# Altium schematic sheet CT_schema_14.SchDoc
size 390 x 385 mm
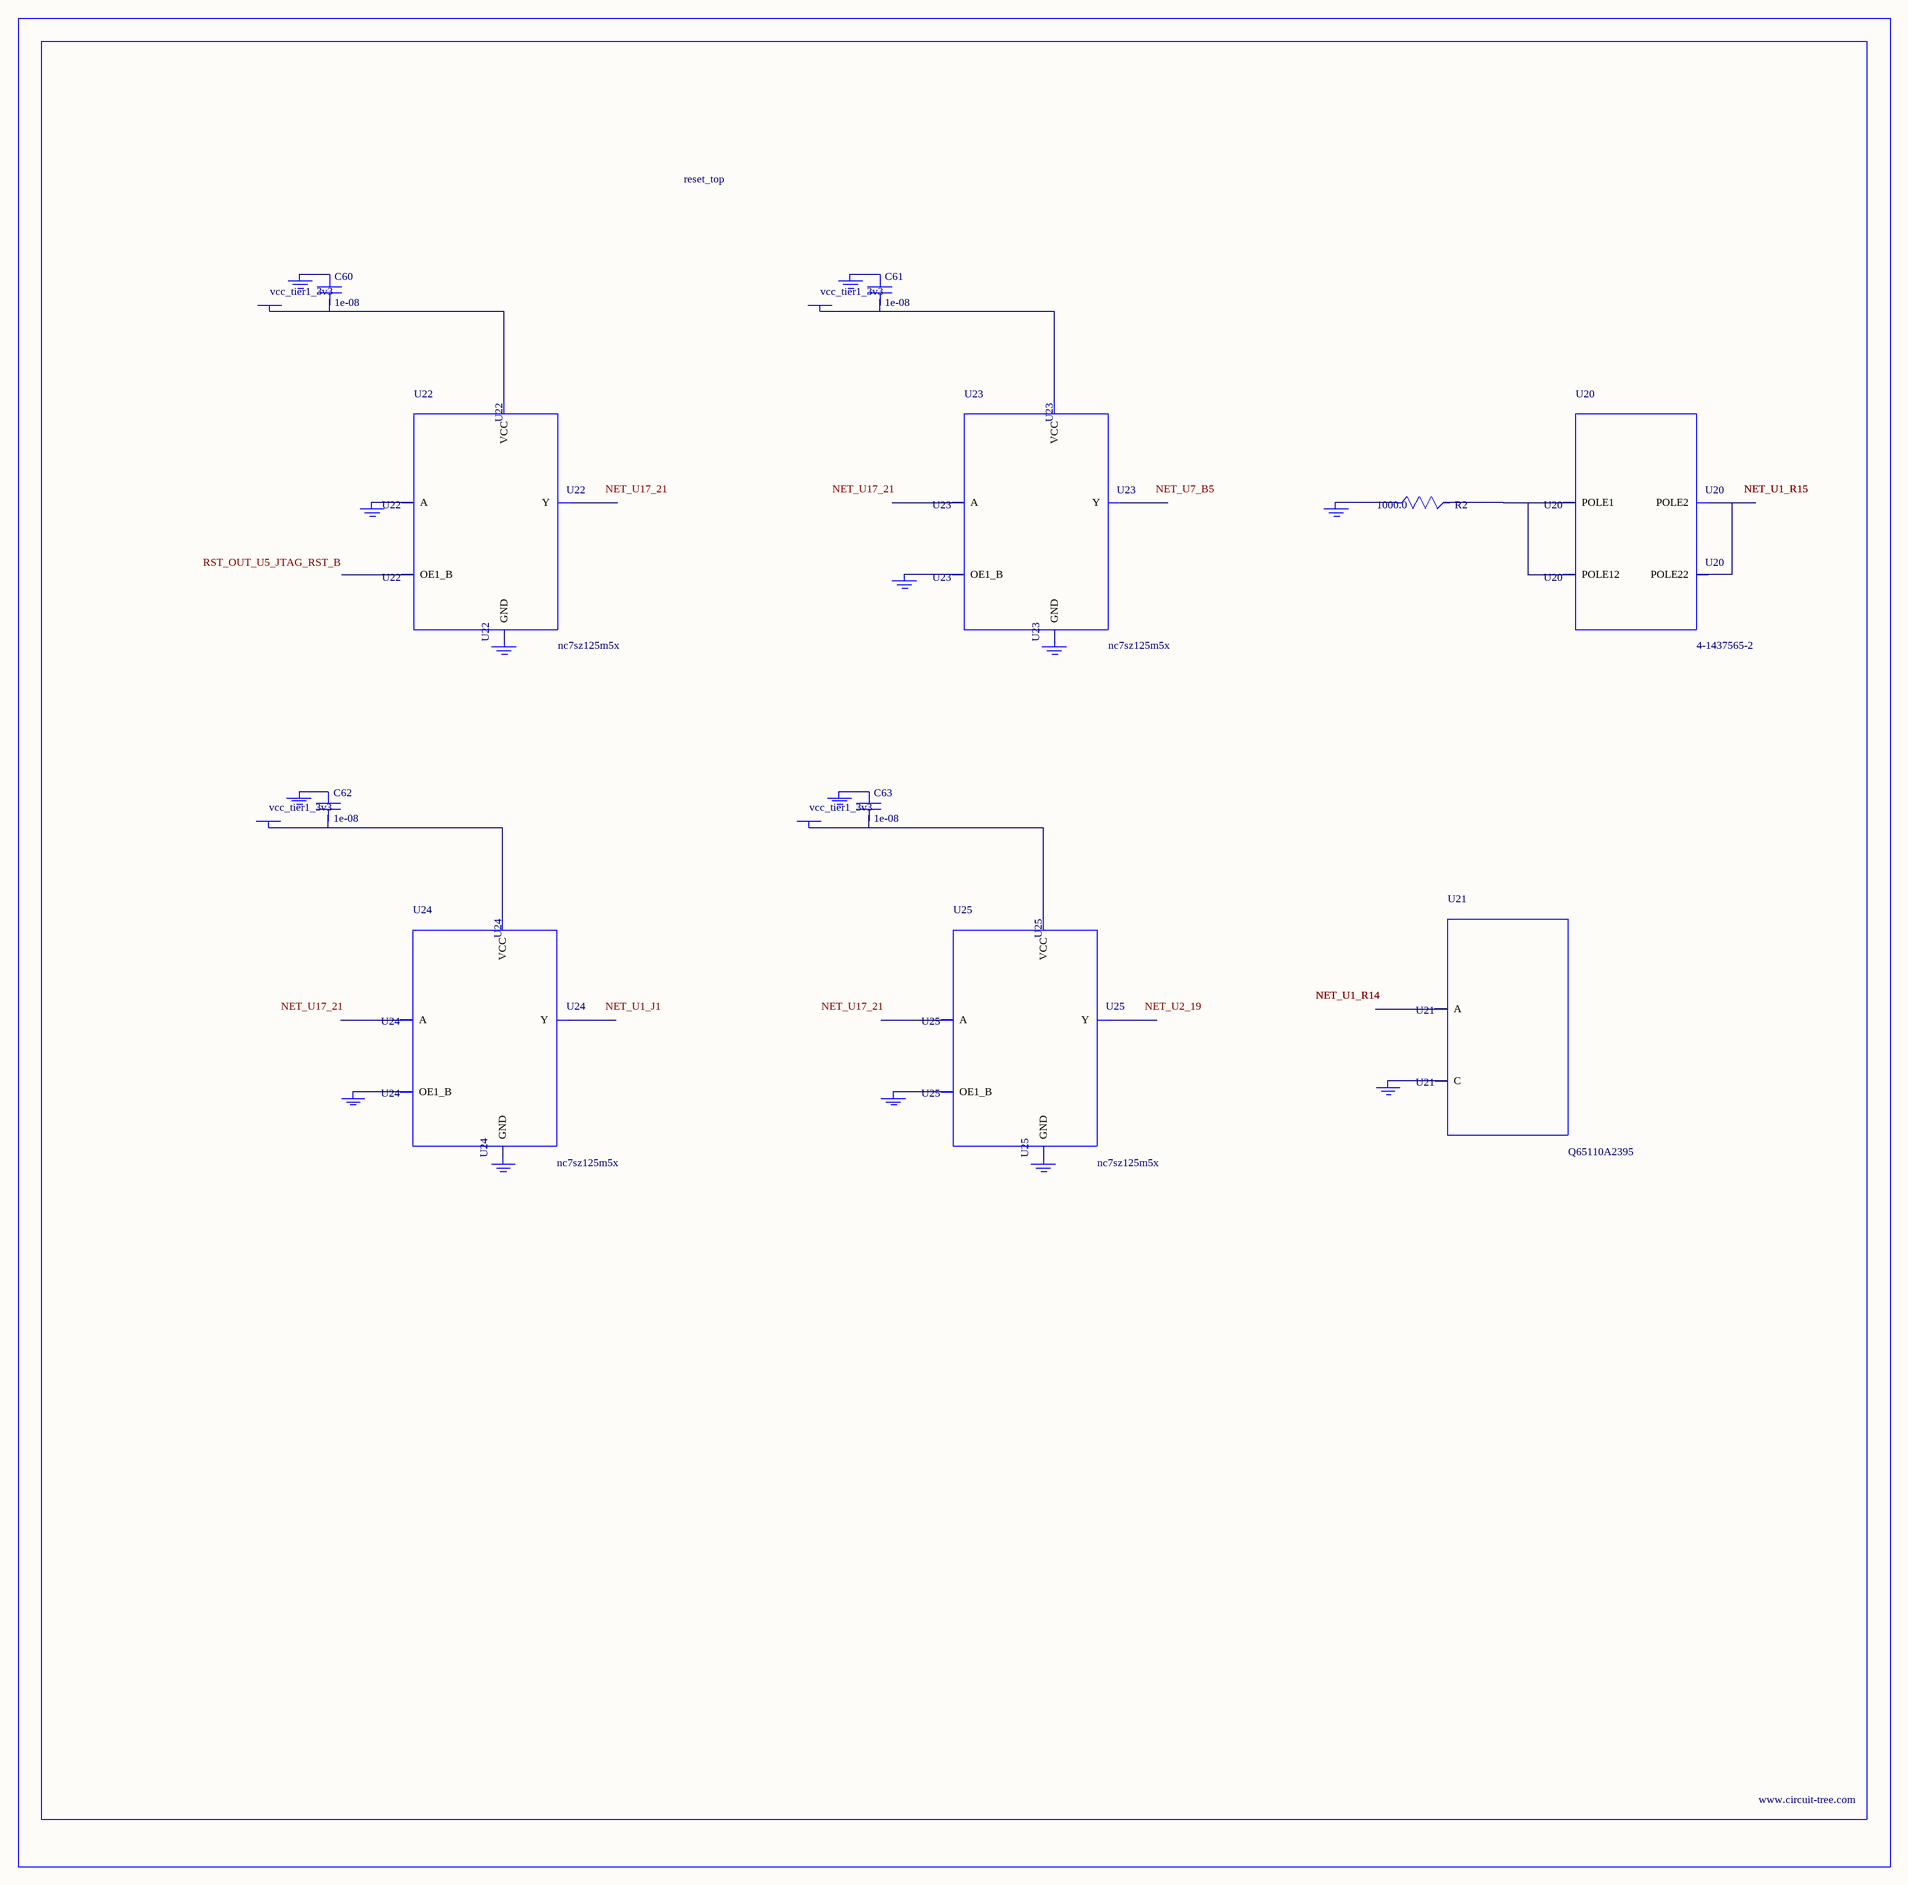
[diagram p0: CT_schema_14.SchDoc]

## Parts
BORDER13  (no value)
C60  1e-08  [C0402]
C61  1e-08  [C0402]
C62  1e-08  [C0402]
C63  1e-08  [C0402]
GND_INSTANCE_13_0  (no value)
GND_INSTANCE_13_1  (no value)
GND_INSTANCE_13_2  (no value)
GND_INSTANCE_13_3  (no value)
GND_INSTANCE_13_4  (no value)
GND_INSTANCE_13_5  (no value)
GND_INSTANCE_13_6  (no value)
GND_INSTANCE_13_7  (no value)
GND_INSTANCE_13_8  (no value)
GND_INSTANCE_13_9  (no value)
GND_INSTANCE_13_10  (no value)
GND_INSTANCE_13_11  (no value)
GND_INSTANCE_13_12  (no value)
GND_INSTANCE_13_13  (no value)
POWER_INSTANCE_13_0  vcc_tier1_3v3
POWER_INSTANCE_13_1  vcc_tier1_3v3
POWER_INSTANCE_13_2  vcc_tier1_3v3
POWER_INSTANCE_13_3  vcc_tier1_3v3
R2  1000.0  [R0603]
U20  4-1437565-2  [SW_4-1437565-2]
U21  Q65110A2395  [LGM67K-G1J2-24-Z]
U22  nc7sz125m5x  [NC7SZ125M5X]
U23  nc7sz125m5x  [NC7SZ125M5X]
U24  nc7sz125m5x  [NC7SZ125M5X]
U25  nc7sz125m5x  [NC7SZ125M5X]

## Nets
NetC60_1: C60.1 GND_INSTANCE_13_2.0(GND)
NetC60_2: C60.2 POWER_INSTANCE_13_0.0(PWR) U22.5(VCC)
NetC61_1: C61.1 GND_INSTANCE_13_5.0(GND)
NetC61_2: C61.2 POWER_INSTANCE_13_1.0(PWR) U23.5(VCC)
NetC62_1: C62.1 GND_INSTANCE_13_8.0(GND)
NetC62_2: C62.2 POWER_INSTANCE_13_2.0(PWR) U24.5(VCC)
NetC63_1: C63.1 GND_INSTANCE_13_11.0(GND)
NetC63_2: C63.2 POWER_INSTANCE_13_3.0(PWR) U25.5(VCC)
NetGND_INSTANCE_13_0_0: GND_INSTANCE_13_0.0(GND) R2.1
NetGND_INSTANCE_13_1_0: GND_INSTANCE_13_1.0(GND) U21.C
NetGND_INSTANCE_13_3_0: GND_INSTANCE_13_3.0(GND) U22.2(A)
NetGND_INSTANCE_13_4_0: GND_INSTANCE_13_4.0(GND) U22.3(GND)
NetGND_INSTANCE_13_6_0: GND_INSTANCE_13_6.0(GND) U23.1(OE1_B)
NetGND_INSTANCE_13_7_0: GND_INSTANCE_13_7.0(GND) U23.3(GND)
NetGND_INSTANCE_13_9_0: GND_INSTANCE_13_9.0(GND) U24.1(OE1_B)
NetGND_INSTANCE_13_10_0: GND_INSTANCE_13_10.0(GND) U24.3(GND)
NetGND_INSTANCE_13_12_0: GND_INSTANCE_13_12.0(GND) U25.1(OE1_B)
NetGND_INSTANCE_13_13_0: GND_INSTANCE_13_13.0(GND) U25.3(GND)
NetR2_2: R2.2 U20.1(POLE1) U20.2(POLE12)
NetU20_3: U20.3(POLE2) U20.4(POLE22)

Not connected (* = marked no-connect by the designer): U21 A; U22 1(OE1_B) 4(Y); U23 2(A) 4(Y); U24 2(A) 4(Y); U25 2(A) 4(Y)

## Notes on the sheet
- Labels drawn without touching a wire or pin: NET_U1_J1, NET_U2_19, NET_U7_B5, NET_U17_21, RST_OUT_U5_JTAG_RST_B

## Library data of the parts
BORDER13 = BORDER_PAGE13
C60-C63 = C0402C103K3RAC
GND_INSTANCE_13_0-GND_INSTANCE_13_13 = GND
POWER_INSTANCE_13_0-POWER_INSTANCE_13_3 = PWR
R2 = RC0603JR-071KL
